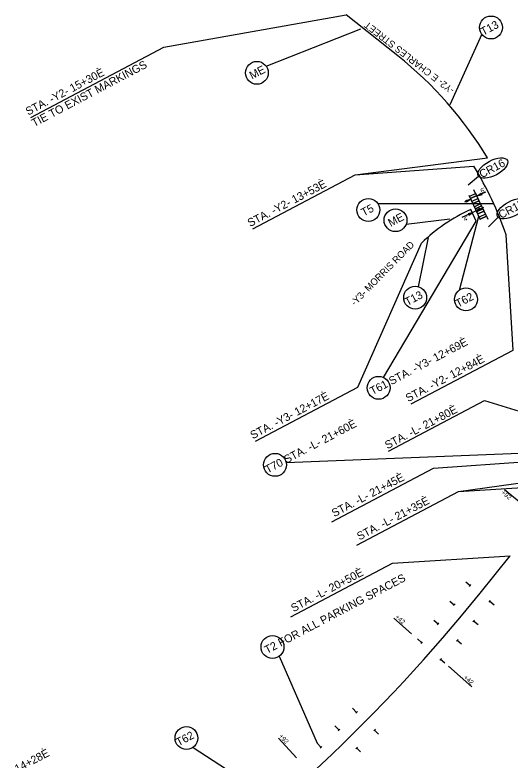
# Model space of a CAD drawing. Extents: x 1487421 to 1489048, y 497792 to 499463.
# Drawn here: x 1488166 to 1488599, y 498768 to 499419 of the extents above; entities that cross this region are included whole.
import ezdxf

# ---------------------------------------------------------------- set-up
doc = ezdxf.new("R2010")
doc.units = 0
for name, color, linetype in [('Prop Dimension', 7, 'Continuous'), ('Prop Dimension Text', 7, 'Continuous'), ('Prop Horizontal Alignment Direction Label', 7, 'Continuous'), ('Prop Mkg Min Skp 6ft White', 7, 'Continuous'), ('Prop Mkg Solid Dbl Yel Rpm 80ft', 7, 'Continuous'), ('Prop Mkg Solid White Crosswalks', 7, 'Continuous'), ('Prop Mkg Solid White Lane Line', 7, 'Continuous'), ('Prop Mkg Solid White Stop Bar', 7, 'Continuous'), ('Scratch_Level_3', 7, 'Continuous'), ('Text', 7, 'Continuous')]:
    doc.layers.add(name, color=color, linetype=linetype)

msp = doc.modelspace()

# ---------------------------------------------------------------- linework, layer by layer
at = {"layer": 'Prop Dimension'}
for p, q in [((1488577.67, 499264.37), (1488570.36, 499260.93)), ((1488564.93, 499258.37), (1488559.46, 499255.79)), ((1488576.13, 499251.04), (1488556.99, 499242.25)), ((1488594.27, 499004.33), (1488608.59, 498992.77)), ((1488497.79, 498891.97), (1488513.26, 498878.31)), ((1488545.42, 498849.89), (1488565.82, 498831.87)), ((1488396.81, 498787.1), (1488412.72, 498769.87))]:
    msp.add_line(p, q, dxfattribs=at)
for points in [[(1488574.78, 499262.08), (1488570.36, 499260.93), (1488574.16, 499263.52), (1488573.96, 499262.56)], [(1488560.54, 499257.14), (1488564.93, 499258.37), (1488561.19, 499255.71), (1488561.37, 499256.68)], [(1488563.13, 499244.37), (1488566.13, 499246.45), (1488562.58, 499245.5), (1488563.26, 499245.12)], [(1488572.77, 499250.19), (1488569.77, 499248.12), (1488573.32, 499249.06), (1488572.63, 499249.44)]]:
    msp.add_lwpolyline(points, close=True, dxfattribs=at)
at = {"layer": 'Prop Mkg Min Skp 6ft White'}
msp.add_arc((1488292.94, 499121.08), 321, 19.31408, 31.13683, dxfattribs=at)
at = {"layer": 'Prop Mkg Solid Dbl Yel Rpm 80ft'}
for p, q in [((1488501.09, 499383.57), (1488455.9, 499419.41)), ((1488573.13, 498913.85), (1488599.3, 498946.31))]:
    msp.add_line(p, q, dxfattribs=at)
for centre, radius, start, end in [((1488292.94, 499121.08), 335, 31.13683, 51.58559), ((1488626.52, 499112.42), 150, 114.273, 134.26172), ((1487424.96, 499839.79), 1475, 305.25533, 321.11565)]:
    msp.add_arc(centre, radius, start, end, dxfattribs=at)
at = {"layer": 'Prop Mkg Solid White Crosswalks'}
for p, q in [((1488580.03, 499240.41), (1488567.75, 499266.47)), ((1488573.44, 499240.32), (1488563.49, 499261.45)), ((1488569.26, 499263.28), (1488563.83, 499260.72)), ((1488569.26, 499263.28), (1488563.83, 499260.72)), ((1488563.83, 499260.72), (1488564.68, 499258.91)), ((1488570.11, 499261.47), (1488564.68, 499258.91)), ((1488564.68, 499258.91), (1488570.11, 499261.47)), ((1488570.11, 499261.47), (1488569.26, 499263.28)), ((1488571.39, 499258.76), (1488565.96, 499256.2)), ((1488571.39, 499258.76), (1488565.96, 499256.2)), ((1488565.96, 499256.2), (1488566.81, 499254.39)), ((1488572.24, 499256.95), (1488566.81, 499254.39)), ((1488566.81, 499254.39), (1488572.24, 499256.95)), ((1488573.52, 499254.23), (1488568.09, 499251.68)), ((1488573.52, 499254.23), (1488568.09, 499251.68)), ((1488572.24, 499256.95), (1488571.39, 499258.76)), ((1488574.37, 499252.42), (1488573.52, 499254.23)), ((1488568.09, 499251.68), (1488568.94, 499249.87)), ((1488574.37, 499252.42), (1488568.94, 499249.87)), ((1488568.94, 499249.87), (1488574.37, 499252.42)), ((1488575.65, 499249.71), (1488570.22, 499247.15)), ((1488575.65, 499249.71), (1488570.22, 499247.15)), ((1488570.22, 499247.15), (1488571.07, 499245.34)), ((1488576.5, 499247.9), (1488571.07, 499245.34)), ((1488571.07, 499245.34), (1488576.5, 499247.9)), ((1488576.5, 499247.9), (1488575.65, 499249.71)), ((1488577.78, 499245.19), (1488572.35, 499242.63)), ((1488577.78, 499245.19), (1488572.35, 499242.63)), ((1488572.35, 499242.63), (1488573.2, 499240.82)), ((1488573.2, 499240.82), (1488578.63, 499243.38)), ((1488578.63, 499243.38), (1488573.2, 499240.82)), ((1488578.63, 499243.38), (1488577.78, 499245.19))]:
    msp.add_line(p, q, dxfattribs=at)
at = {"layer": 'Prop Mkg Solid White Lane Line'}
for p, q in [((1488560.48, 498923.67), (1488564.38, 498920.53)), ((1488563.75, 498919.75), (1488565, 498921.3)), ((1488580.87, 498905.94), (1488582.13, 498907.49)), ((1488546.69, 498906.83), (1488550.54, 498903.63)), ((1488549.88, 498902.88), (1488551.2, 498904.38)), ((1488581.5, 498906.72), (1488585.39, 498903.58)), ((1488532.65, 498890.2), (1488536.45, 498886.95)), ((1488566.79, 498888.82), (1488568.12, 498890.32)), ((1488567.45, 498889.57), (1488571.3, 498886.37)), ((1488535.81, 498886.18), (1488537.09, 498887.72)), ((1488518.37, 498873.79), (1488522.12, 498870.48)), ((1488521.45, 498869.73), (1488522.78, 498871.23)), ((1488552.51, 498871.87), (1488553.8, 498873.4)), ((1488553.15, 498872.63), (1488556.95, 498869.38)), ((1488537.94, 498855.16), (1488539.27, 498856.66)), ((1488542.35, 498852.6), (1488538.6, 498855.91)), ((1488461.61, 498813.12), (1488465.17, 498809.6)), ((1488464.43, 498808.92), (1488465.9, 498810.28)), ((1488446.19, 498797.77), (1488449.69, 498794.2)), ((1488448.95, 498793.52), (1488450.42, 498794.88)), ((1488480.06, 498793.44), (1488481.53, 498794.8)), ((1488480.8, 498794.12), (1488484.41, 498790.66)), ((1488430.53, 498782.66), (1488433.98, 498779.04)), ((1488433.24, 498778.36), (1488434.71, 498779.71)), ((1488464.35, 498777.81), (1488465.82, 498779.17)), ((1488465.08, 498778.49), (1488468.64, 498774.98))]:
    msp.add_line(p, q, dxfattribs=at)
at = {"layer": 'Prop Mkg Solid White Stop Bar'}
msp.add_line((1488569.55, 499239.2), (1488564.85, 499249.18), dxfattribs=at)
at = {"layer": 'Scratch_Level_3'}
msp.add_line((1488322.17, 498778.92), (1488393.88, 498732.71), dxfattribs=at)
msp.add_circle((1488316.41, 498787.09), 10, dxfattribs=at)
at = {"layer": 'Text'}
for p, q in [((1488296.67, 499391.16), (1488455.9, 499419.41)), ((1488386.15, 499374.53), (1488468.87, 499407.31)), ((1488574.49, 499402.66), (1488546.54, 499340.74)), ((1488180.49, 499329.82), (1488296.67, 499391.16)), ((1488463.77, 499279.5), (1488579.68, 499294.31)), ((1488463.77, 499279.5), (1488567.7, 499287.07)), ((1488374.55, 499232.38), (1488463.77, 499279.5)), ((1488562.53, 499270.86), (1488571.72, 499278.33)), ((1488483.6, 499254.63), (1488584.96, 499254.38)), ((1488508.49, 499236.4), (1488546.6, 499241.03)), ((1488554.99, 499178.8), (1488571.98, 499243.42)), ((1488580.42, 499234.25), (1488588.74, 499242.5)), ((1488488.79, 499102.33), (1488569.55, 499239.2)), ((1488601.93, 499126.36), (1488595.88, 499227.25)), ((1488519.35, 499181.68), (1488528.04, 499224.9)), ((1488466.11, 499093.88), (1488521.83, 499219.84)), ((1488512.71, 499079.25), (1488601.93, 499126.36)), ((1488376.89, 499046.77), (1488466.11, 499093.88)), ((1488492.96, 499037.96), (1488576.94, 499082.31)), ((1488576.94, 499082.31), (1488676.79, 499051.16)), ((1488403.63, 499028), (1488669.38, 499038.88)), ((1488532.23, 499023.09), (1488645.98, 499031.28)), ((1488443.39, 498976.18), (1488532.23, 499023.09)), ((1488554.22, 499002.72), (1488648.38, 499015.93)), ((1488554.22, 499002.72), (1488656.94, 499009.02)), ((1488465.39, 498955.81), (1488554.22, 499002.72)), ((1488407.75, 498893.1), (1488496.58, 498940.01)), ((1488496.58, 498940.01), (1488599.3, 498946.31)), ((1488397.37, 498858.6), (1488430.53, 498782.66))]:
    msp.add_line(p, q, dxfattribs=at)
for centre in [(1488582.66, 499408.42), (1488377.97, 499368.77), (1488475.42, 499248.87), (1488499.13, 499239.9), (1488516.3, 499172.16), (1488560.75, 499170.63), (1488484.36, 499093.36), (1488393.84, 499025.98), (1488391.61, 498866.78)]:
    msp.add_circle(centre, 10, dxfattribs=at)
for centre in [(1488584.19, 499285.45), (1488600.98, 499249.9)]:
    msp.add_ellipse(centre, major_axis=(12.73, 6.72), ratio=0.462467, dxfattribs=at)

# ---------------------------------------------------------------- texts
at = {"layer": 'Prop Dimension'}
for s, p in [("6'", (1488574.58, 499263.28)), ("4'", (1488559.72, 499238.63))]:
    msp.add_text(s, height=4, rotation=26.23364, dxfattribs=at).set_placement(p)
at = {"layer": 'Prop Dimension Text'}
for s, rotation, p in [('+92', 321.11565, (1488591.24, 499001.13)), ('+42', 318.54019, (1488498.47, 498892.45)), ('+42', 318.54019, (1488558.3, 498839.59)), ('+92', 312.7135, (1488396.91, 498788.46))]:
    msp.add_text(s, height=4, rotation=rotation, dxfattribs=at).set_placement(p)
at = {"layer": 'Prop Horizontal Alignment Direction Label'}
for s, rotation, p in [('-Y2- E CHARLES STREET', 142.12709, (1488551.16, 499354.6)), ('-Y3- MORRIS ROAD', 45.44455, (1488463.55, 499164.63))]:
    msp.add_text(s, height=6, rotation=rotation, dxfattribs=at).set_placement(p)
at = {"layer": 'Scratch_Level_3'}
msp.add_text('T62', height=7, rotation=27.835, dxfattribs=at).set_placement((1488309.52, 498779.77))
at = {"layer": 'Text'}
for s, rotation, p in [('T13', 27.835, (1488575.82, 499401.12)), ('TIE TO EXIST MARKINGS', 27.83501, (1488183.33, 499321.26)), ('STA. -Y2- 15+30È', 27.83501, (1488178.02, 499331.32)), ('ME', 27.835, (1488373.73, 499362.85)), ('CR16', 27.83509, (1488574.61, 499276.5)), ('STA. -Y2- 13+53È', 27.83501, (1488372.07, 499233.88)), ('T5', 27.835, (1488471.33, 499243.02)), ('CR15', 27.83509, (1488591.47, 499240.98)), ('ME', 27.835, (1488494.89, 499233.98)), ('T13', 27.835, (1488509.46, 499164.85)), ('T62', 27.835, (1488553.87, 499163.3)), ('T61 STA. -Y3- 12+69È', 27.835, (1488479.03, 499086.86)), ('STA. -Y2- 12+84È', 27.83501, (1488510.24, 499080.75)), ('STA. -Y3- 12+17È', 27.83501, (1488374.42, 499048.27)), ('STA. -L- 21+80È', 27.835, (1488492.1, 499039.53)), ('T70 STA. -L- 21+60È', 27.835, (1488387.37, 499018.32)), ('STA. -L- 21+45È', 27.83501, (1488445.64, 498980.18)), ('STA. -L- 21+35È', 27.83501, (1488467.64, 498959.81)), ('STA. -L- 20+50È', 27.83501, (1488410, 498897.1)), ('T2 FOR ALL PARKING SPACES', 27.835, (1488386.84, 498860.57)), ('STA. -L- 14+28È', 27.83501, (1488135.4, 498739.14))]:
    msp.add_text(s, height=7, rotation=rotation, dxfattribs=at).set_placement(p)

doc.saveas('drawing.dxf')
